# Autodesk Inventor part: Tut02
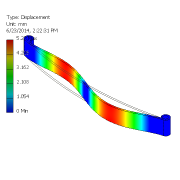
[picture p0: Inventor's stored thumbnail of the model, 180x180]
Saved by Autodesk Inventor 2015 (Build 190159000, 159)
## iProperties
Created: 2013-01
Part Number: Tut02
Material: Steel, Mild
Document SubType Name: Modeling
Designer: CADCIM
Density: 7.86 g/cm^3
Appearance: Steel
Mass: 9.78337 g
Surface Area: 26.8047 cm^2
Volume: 1.2447 cm^3
Author: CADCIM
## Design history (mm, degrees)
sketch "Sketch1"
  geometry: L1 (-48.188, 1.022)-(-47.141, 0.956); L2 (48.275, 0.799)-(47.214, 0.677); A1 r 200 centre (0, 193.649) between (-50, 0) and (50, 0); A2 r 201.033 centre (0, 193.649) between (-50.258, -1) and (50.258, -1); A3 r 1.5 centre (-49.625, 1.452) between (-48.188, 1.022) and (-50, 0); A4 r 2.533 centre (-49.625, 1.452) between (-47.141, 0.956) and (-50.258, -1); A5 r 1.5 centre (49.625, 1.452) between (50, 0) and (48.275, 0.799); A6 r 2.533 centre (49.625, 1.452) between (50.258, -1) and (47.214, 0.677); 1 further point
  constraints: 12 point on circle, 6 centre point, 4 end point, 4 tangent, 1 horizontal alignment
  dimensions: "d0" = 100 distance of A1.start A1.end; "d1" = 200 radius of A1; "d2" = 50 distance of point (0, 0) A1.start; "d3" = 1 vertical distance of A2.start A1.start; "d4" = 3 diameter of A3; "d5" = 3 diameter of A5
extrude "Extrusion1" new body sketch "Sketch1" distance "d6" = 10; taper "d7" = 0 deg
body "Solid1"
